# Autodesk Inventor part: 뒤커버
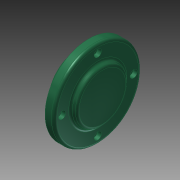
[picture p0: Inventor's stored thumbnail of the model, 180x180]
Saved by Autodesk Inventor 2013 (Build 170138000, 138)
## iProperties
Created: 2015-11
Part Number: 뒤커버
Material: 알루미늄 6061
Document SubType Name: Modeling
Designer: mduedu
Density: 2.71 g/cm^3
Mass: 279.258 g
Surface Area: 218.413 cm^2
Volume: 103.047 cm^3
Author: mduedu
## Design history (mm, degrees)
sketch "스케치1"
  geometry: C1 r 47.5 at (0, 0); 1 further point
  constraints: 1 centre point, 1 coincident
  dimensions: "d42" = 95 diameter of C1
extrude "돌출1" new body sketch "스케치1" distance "d3" = 10; taper "d4" = 0 deg
sketch "스케치2"
  geometry: C1 r 30 at (0, 0); 1 further point
  constraints: 1 centre point, 1 coincident
  dimensions: "d5" = 60 diameter of C1
extrude "돌출2" join sketch "스케치2" distance "d6" = 5; taper "d7" = -30 deg
sketch "스케치5" dims "d44" = 78
  geometry: 3 further points
  constraints: 2 vertical alignment, 1 coincident, 2 other
hole "구멍3" sketch "스케치5" at (0, 39) diameter "d45" = 4.5; stored, may be unused: countersink angle "d49" = 90 deg, drill point angle "d51" = 118 deg; dims "d46" = 6, "d47" = 8, "d48" = 4.4, "d50" = 8
sketch "스케치4"
  geometry: C1 r 32.5 at (0, 0); 1 further point
  constraints: 1 centre point, 1 coincident
  dimensions: "d21" = 65 diameter of C1
extrude "돌출3" join sketch "스케치4" distance "d23" = 12; taper "d24" = 0 deg
hole "구멍2" diameter "d27" = 34; stored, may be unused: countersink angle "d31" = 90 deg, drill point angle "d33" = 0 deg; dims "d28" = 6, "d29" = 40, "d30" = 12, "d32" = 16, "d61" = 10, "d64" = 10
fillet "모깎기3" dims "d36" = 3
fillet "모깎기4" dims "d37" = 3
fillet "모깎기5" dims "d38" = 0.3
chamfer "모따기1" distance "d39" = 1; stored, may be unused: second distance "d40" = 2, angle "d41" = 45 deg
node "솔리드1"
pattern_circular "원형 패턴2" dims angle "d53" = 360 deg
